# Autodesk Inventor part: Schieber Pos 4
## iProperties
Created: 2009-11
Part Number: Schieber Pos 4
Document SubType Name: Modeling
Designer: user
Author: user
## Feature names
1. Extrusion1
2. Extrusion2
3. Extrusion3
